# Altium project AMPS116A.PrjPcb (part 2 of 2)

## Sheet AMPS116A_PowerSupplies.SchDoc: Power Supplies
size Letter; Date: Not shown in title block; ApprovedBy: Not shown in title block; CheckedBy: Not shown in title block; Author: Not shown in title block; CompanyName: Not shown in title block; DrawnBy: GJS; Engineer: Not shown in title block; Organization: Not shown in title block; Address1: Not shown in title block; Address2: Not shown in title block; Address3: Not shown in title block; Address4: Not shown in title block; DocumentNumber: 5; SheetNumber: 5; SheetTotal: 6; PageSetup: Record=PageOptions¦CenterHorizontal=True¦CenterVertical=True¦PrintScale=0.70¦XCorrection=1.00¦YCorrection=1.00¦PrintKind=0¦BorderSize=5000000¦LeftOffset=0¦BottomOffset=0¦Orientation=2¦PaperLength=1000¦PaperWidth=1000¦Scale=100¦PaperSource=15¦PrintQuality=600¦MediaType=1¦DitherType=10¦PrintScaleMode=1¦PaperKind=Letter
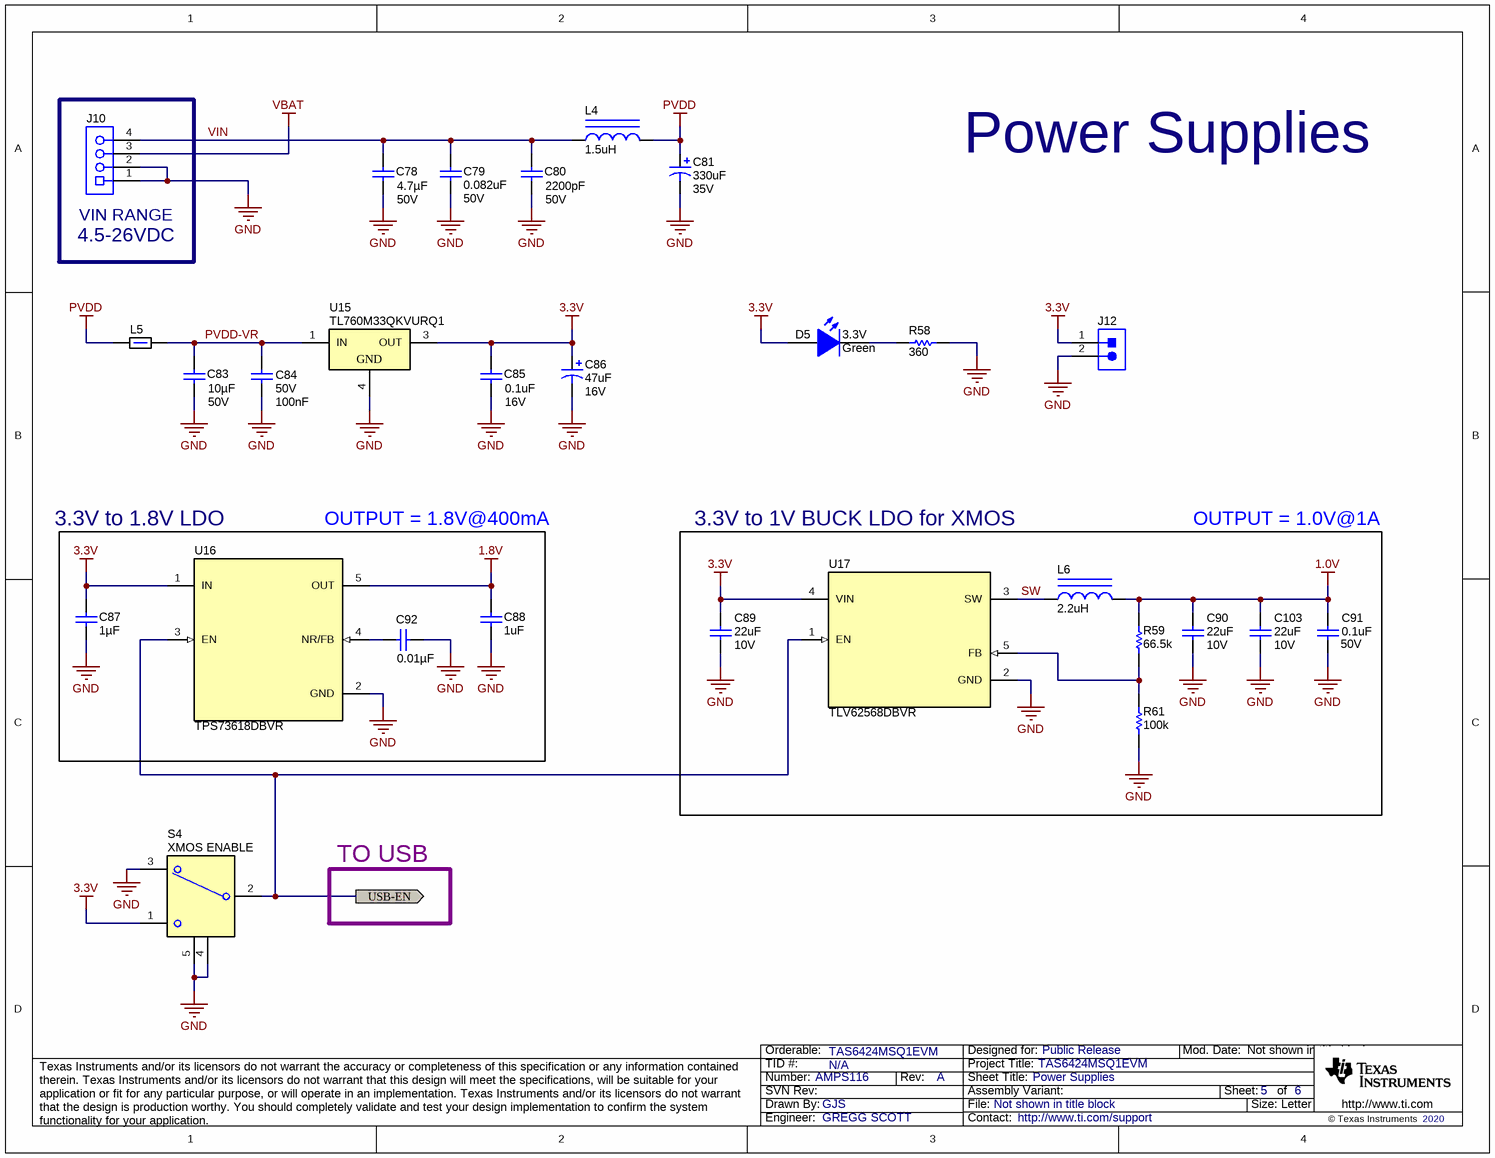
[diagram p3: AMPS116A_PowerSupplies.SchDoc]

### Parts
C78  VDC_V: 50V  ValueDisplayed: 4.7µF  [1210_280]  (hidden comment: C1210C475K5RACAUTO)
C79  ValueDisplayed: 0.082uF  VDC_V: 50V  [0805L]  (hidden comment: Capacitor)
C80  VDC_V: 50V  ValueDisplayed: 2200pF  [0805L]  (hidden comment: 08055A222JAT2A)
C81  ValueDisplayed: 330uF  VDC_V: 35V  [BT_1000x2000]  (hidden comment: +)
C83  VDC_V: 50V  ValueDisplayed: 10µF  [1206_190L]  (hidden comment: UMK316BBJ106KL-T)
C84  Cap_F: 100nF  VDC_V: 50V  [0603L]  (hidden comment: C0603C104J5RACTU)
C85  VDC_V: 16V  ValueDisplayed: 0.1uF  [0402L]  (hidden comment: C0402C104K4RACAUTO)
C86  ValueDisplayed: 47uF  VDC_V: 16V  [FC_500x1100]  (hidden comment: Cap_Polarized)
C87  ValueDisplayed: 1µF  [0603L]  (hidden comment: CL10B105MO8NNWC)
C88  ValueDisplayed: 1uF  [0402L]  (hidden comment: GRM152R60J105ME15D)
C89  VDC_V: 10V  ValueDisplayed: 22uF  [0603L]  (hidden comment: C1608X5R1A226M080AC)
C90  VDC_V: 10V  ValueDisplayed: 22uF  [0603L]  (hidden comment: C1608X5R1A226M080AC)
C91  VDC_V: 50V  ValueDisplayed: 0.1uF  [0402L]  (hidden comment: C1005X7R1H104K050BB)
C92  ValueDisplayed: 0.01µF  [0402L]  (hidden comment: 0402B103K6R3CT)
C103  VDC_V: 10V  ValueDisplayed: 22uF  [0603L]  (hidden comment: C1608X5R1A226M080AC)
D5  3.3V  value Green  [LTST-C170KGKT_Green]
J10  Receptacle_4x1  [TERM_BLK_ED555-4DS]  (value not drawn)
J12  DNP  [Sullins_PBC02SAAN]  (value not drawn)
L4  ValueDisplayed: 1.5uH  [VCMT053T]  (hidden comment: VCMT053T-1R5MN5)
L5  Ferrite_Bead  [NFZ2M]  (value not drawn)
L6  ValueDisplayed: 2.2uH  [1008]  (hidden comment: LQM2HPN2R2MG0L)
R58  ValueDisplayed: 360  [0402L]  (hidden comment: Resistor)
R59  ValueDisplayed: 66.5k  [0603L]  (hidden comment: RC0603FR-0766K5L)
R61  ValueDisplayed: 100k  [0603L]  (hidden comment: RC0603FR-07100KL)
S4  XMOS ENABLE  [SW_FT1D-4M-Z]
U15  PartNumber: TL760M33QKVURQ1  [KVU0003A_N]  (hidden comment: TI-TL7X0MXX-Q1KVU3)
U16  PartNumber: TPS73618DBVR  [DBV0005A_N]  (hidden comment: TPS736xxDBV)
U17  TLV62568DBVR  [DBV0005A_N]

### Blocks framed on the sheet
4.5-26VDC: J10
3.3V to 1.8V LDO: C87 C88 C92 U16
3.3V to 1V BUCK LDO for XMOS: C89-C91 C103 L6 R59 R61 U17

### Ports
USB-EN (out)

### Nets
1.0V: C90.1 C91.1 C103.1 L6.2 R59.2
1.8V: C88.2 U16.5(OUT)
3.3V: C85.2 C86.1(+) C87.2 C89.1 D5.1(A) J12.1 S4.1 U15.3(OUT) U16.1(IN) U17.4(VIN)
GND: C78.1 C79.1 C80.2 C81.2(-) C83.2 C84.1 C85.1 C86.2(-) C87.1 C88.1 C89.2 C90.2 C91.2 C92.1 C103.2 J10.1 J10.2 J12.2 R58.2 R61.1 S4.3 S4.4 S4.5 U15.4(GND) U16.2(GND) U17.2(GND)
PVDD: C81.1(+) L4.2 L5.1
VBAT: J10.3
PVDD-VR: C83.1 C84.2 L5.2 U15.1(IN)
SW: L6.1 U17.3(SW)
USB-EN: S4.2(COM) U16.3(EN) U17.1(EN) ; port USB-EN
VIN: C78.2 C79.2 C80.1 J10.4 L4.1
NetC92_2: C92.2 U16.4(NR/FB)
NetD5_2: D5.2(K) R58.1
NetR59_1: R59.1 R61.2 U17.5(FB)

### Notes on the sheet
- Power Supplies
- (near J10) VIN RANGE
- OUTPUT = 1.8V@400mA
- OUTPUT = 1.0V@1A
- TO USB

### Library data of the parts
C78 = CMP-0079604-1: CAP, CERM, 4.7 µF, 50 V,+/- 10%, X7R, AEC-Q200 Grade 1, 1210; Manufacturer: Kemet; TaMin_C: -55°C; Polarized: N; SizeAreaWB_mm2: 14.7; U/M: EA; Value: 4.7uF; TaMax_C: 125°C; SizeZ_mm: 2.8; SizeX_mm: 3.2; SizeY_mm: 2.5; Cap_Case: 1210; SizeArea_mm2: 8; AEC Qualified: Y; AEC Grade: 1; AEC Category: Q200
C79 = CMP-0007669-2: CAP, CERM, 0.082 uF, 50 V, +/- 10%, X7R, 0805; PartNumber: 08055C823KAT2A; Manufacturer: AVX; Polarized: N; U/M: EA; Cap_F: 82nF; ESR_ohm: 0.026; Value1: 0.026 ohm; TaMin_C: -55°C; TaMax_C: 125°C; Cap_Case: 0805; AEC Category: Q200; SizeArea_mm2: 2.5; SizeAreaWB_mm2: 6.75; SizeX_mm: 2; SizeY_mm: 1.25; SizeZ_mm: 1.45
C80 = CMP-0007601-2: CAP, CERM, 2200 pF, 50 V, +/- 5%, C0G/NP0, 0805; Manufacturer: AVX; TaMin_C: -55°C; ESR_ohm: 0.08; Polarized: N; SizeAreaWB_mm2: 6.75; Value1: 0.08 ohm; U/M: EA; Value: 2200pF; TaMax_C: 125°C; SizeZ_mm: 1.45; SizeX_mm: 2; SizeY_mm: 1.25; Cap_Case: 0805; SizeArea_mm2: 2.5; Cap_F: 2.2nF; AEC Category: Q200
C81 = CMP-0010530-2: CAP, AL, 330 uF, 35 V, +/- 20%, AEC-Q200 Grade 1, TH; PartNumber: UBT1V331MPD1TD; Manufacturer: Nichicon; Polarized: Y; CompType: Capacitor; Value: 330uF; U/M: EA; Cap_F: 330µF; Value1: Unknown; TaMin_C: -40°C; TaMax_C: 125°C; Cap_Case: 10x20mm; AEC Category: Q200; AEC Grade: 1; SizeArea_mm2: 100; SizeAreaWB_mm2: 144; SizeX_mm: 10; SizeZ_mm: 22
C83 = CMP-0086153-1: CAP, CERM, 10 µF, 50 V,+/- 10%, X5R, 1206; Manufacturer: Taiyo Yuden; Polarized: N; SizeX_mm: 3.2; TaMax_C: 85°C; SizeY_mm: 1.6; AEC Category: Q200; SizeArea_mm2: 5.12; Cap_Case: 1206; SizeAreaWB_mm2: 10.92; TaMin_C: -55°C; SizeZ_mm: 1.9; U/M: EA; Value: 10uF
C84 = CMP-0006858-4: CAP, CERM, 0.1 uF, 50 V, +/- 5%, X7R, 0603; Manufacturer: Kemet; TaMin_C: -55°C; Polarized: N; SizeAreaWB_mm2: 4.68; Value1: Unknown; U/M: EA; Value: 0.1uF; TaMax_C: 125°C; SizeZ_mm: 1; SizeX_mm: 1.6; SizeY_mm: 0.8; Cap_Case: 0603; SizeArea_mm2: 1.28; AEC Category: Q200
C85 = CMP-0006237-2: CAP, CERM, 0.1 uF, 16 V, +/- 10%, X7R, AEC-Q200 Grade 1, 0402; Manufacturer: Kemet; TaMin_C: -55°C; Polarized: N; SizeAreaWB_mm2: 3; Value1: Unknown; U/M: EA; Value: 0.1uF; TaMax_C: 125°C; SizeZ_mm: 0.6; SizeX_mm: 1; SizeY_mm: 0.5; Cap_Case: 0402; AEC Qualified: Y; Cap_F: 100nF; AEC Category: Q200
C86 = CMP-0010336-1: CAP, AL, 47 uF, 16 V, +/- 20%, 0.8 ohm, AEC-Q200 Grade 2, TH; PartNumber: EEU-FC1C470; Manufacturer: Panasonic; Polarized: Y; CompType: Capacitor; Value: 47uF; U/M: EA; Cap_F: 47µF; ESR_ohm: 8d; Value1: 0.8 ohm; IRMS_A: 1.75dA; TaMin_C: -55°C; TaMax_C: 105°C; Cap_Case: 5x11mm; AEC Category: Q200; AEC Grade: 2; SizeArea_mm2: 25; SizeAreaWB_mm2: 49; SizeX_mm: 5; SizeZ_mm: 12
C87 = CMP-0082012-1: CAP, CERM, 1 µF, 16 V,+/- 20%, X7R, 0603; Manufacturer: Samsung; SizeAreaWB_mm2: 4.68; SizeArea_mm2: 1.28; AEC Qualified: N; AEC Category: Q200; Value: 1uF; TaMax_C: 125°C; SizeZ_mm: 1; TaMin_C: -55°C; VDC_V: 16V; SizeY_mm: 0.8; U/M: EA; CompType: Capacitor; SizeX_mm: 1.6; Cap_Case: 0603
C88 = CMP-0006372-2: CAP, CERM, 1 uF, 6.3 V, +/- 20%, X5R, 0402; Manufacturer: MuRata; TaMin_C: -55°C; Polarized: N; SizeAreaWB_mm2: 3; Value1: Unknown; U/M: EA; Value: 1uF; TaMax_C: 85°C; SizeZ_mm: 0.6; SizeX_mm: 1; SizeY_mm: 0.5; Cap_Case: 0402; Value2: 6.3V; CompType: Capacitor; Cap_F: 1µF; AEC Category: Q200
C89 C90 C103 = CMP-0007005-5: CAP, CERM, 22 uF, 10 V, +/- 20%, X5R, 0603; Manufacturer: TDK; TaMin_C: -55°C; ESR_ohm: 3.71m; Polarized: N; SizeAreaWB_mm2: 4.68; Value1: 0.00371 ohm; U/M: EA; Value: 22uF; TaMax_C: 85°C; SizeZ_mm: 1; SizeX_mm: 1.6; SizeY_mm: 0.8; Cap_Case: 0603; SizeArea_mm2: 1.28; CompType: Capacitor; Cap_F: 22µF; IRMS_A: 2.69936A; AEC Category: Q200
C91 = CMP-0006297-2: CAP, CERM, 0.1 uF, 50 V, +/- 10%, X7R, 0402; Manufacturer: TDK; TaMin_C: -55°C; Polarized: N; SizeAreaWB_mm2: 3; Value1: 0.039064 ohm; U/M: EA; Value: 0.1uF; TaMax_C: 125°C; SizeZ_mm: 0.6; SizeX_mm: 1; SizeY_mm: 0.5; Cap_Case: 0402; Cap_F: 100nF; AEC Category: Q200; ESR_ohm: 0.039064; IRMS_A: 8.14669dA
C92 = CMP-0860544-1: CAP, CERM, 0.01 µF, 6.3 V,+/- 10%, X7R, 0402; Manufacturer: Walsin; Value: 0.01uF; SizeY_mm: 0.5; SizeX_mm: 1; SizeZ_mm: 0.6; AEC Category: Q200; Value2: 6.3V; SizeAreaWB_mm2: 3; TaMax_C: 125°C; U/M: EA; Cap_Case: 0402; AEC Qualified: N; Cap_F: 10nF; TaMin_C: -55°C
D5 = CMP-0002888-2: LED, Green, SMD; Manufacturer: Lite-On; PartNumber: LTST-C170KGKT; Value1: W; Vf_V: 2V; Type: AlInGaP; Io_A: 20mA
J10 = CMP-0074917-1: Terminal Block, 3.5mm Pitch, 4x1, TH; PartNumber: ED555/4DS; Manufacturer: On-Shore Technology; Pitch_mm: 3.5; Gender: Female; Shrouded: N; Row_Count: 1; ContactFinish: Brass; Current_A: 6A; Voltage_V: 150V; Cert_CULUS: Y; CNHeader: False; CT: True; Green_Lifecycle: Not Set; Green_REACh: Incomplete
J12 = CMP-0054566-1: Header, 100mil, 2x1, Gold, TH; PartNumber: PBC02SAAN; Manufacturer: Sullins Connector Solutions; Cert_UL: Y; CNHeader: TRUE; CT: FALSE; Current_A: 3A; Gender: Male; Green_Lifecycle: Active; Green_REACh: Passed; Pitch_mm: 2.54; Row_Count: 1; Shrouded: N; Voltage_V: 1.8kV
L4 = CMP-0059922-1: Inductor, 1.5 uH, 5.5 A, 0.017 ohm, AEC-Q200 Grade 0, SMD; Manufacturer: Cyntec; Isat: 5.5A @ 30% inductance drop; Irms: 7.4A @ 40C rise; SizeAreaWB_mm2: 54.0125; DCR_ohm: 0.017; Value: 1.5uH; Imax_A: 5.5A; SizeZ_mm: 3; SizeX_mm: 5.45; SizeY_mm: 5.25; SizeArea_mm2: 28.6125; Ind_H: 1.5µH; AEC Qualified: Y; AEC Grade: 0; AEC Category: Q200
L5 = CMP-0003430-1: Ferrite Bead, 180 ohm @ 100 MHz, 3.4 A, 0806; PartNumber: NFZ2MSM181SN10L; Manufacturer: MuRata; Value: 180 ohm; Imax_A: 3.4A; DCR_ohm: 0.025; Value1: 0.025 ohm; ZTyp@100MHz_Ohm: 180
L6 = CMP-0058752-1: Inductor, Multilayer, Ferrite, 2.2 uH, 1.3 A, 0.08 ohm, SMD; Manufacturer: MuRata; Irms: 1.3A @ 40C rise; Green_Lifecycle: Active; SizeAreaWB_mm2: 10.5; DCR_ohm: 0.08; Green_REACh: Passed; Value: 2.2uH; Imax_A: 1.3A; SizeZ_mm: 1.2; SizeX_mm: 2.5; SizeY_mm: 2; SizeArea_mm2: 5; Ind_H: 2.2µH; AEC Category: Q200
R58 = CMP-0026910-3: RES, 360, 5%, 0.063 W, AEC-Q200 Grade 0, 0402; PartNumber: CRCW0402360RJNED; Manufacturer: Vishay-Dale; Value: 360; Value_Code: 360R; Power_W: 63mW; Value2: 0.063W; VDC_V: 50V; TempCo: 200 ppm/C; EIA_Code: E24; AEC Category: Q200; AEC Grade: 0; AEC Qualified: Y; SizeArea_mm2: 0.5; SizeX_mm: 1; SizeZ_mm: 0.6
R59 = CMP-0023232-5: RES, 66.5 k, 1%, 0.1 W, 0603; Manufacturer: Yageo; Power_W: 100mW; TempCo: 100 ppm/C; Value_Code: 66k5; Value: 66.5k; EIA_Code: E96; SizeZ_mm: 1; Value2: 0.1W; SizeArea_mm2: 1.28; AEC Qualified: N; VDC_V: 75V; AEC Category: Q200; SizeAreaWB_mm2: 4.68; SizeX_mm: 1.6; SizeY_mm: 0.8
R61 = CMP-0022735-5: RES, 100 k, 1%, 0.1 W, 0603; Manufacturer: Yageo; Power_W: 100mW; TempCo: 100 ppm/C; Value: 100k; EIA_Code: E96; SizeX_mm: 1.6; SizeY_mm: 0.8; SizeZ_mm: 1; Value2: 0.1W; SizeArea_mm2: 1.28; AEC Qualified: N; VDC_V: 75V; AEC Category: Q200; SizeAreaWB_mm2: 4.68
S4 = CMP-0002268-2: Switch, SPDT, On-On, 1 Pos, 0.4A, 28 VDC, TH; PartNumber: FT1D-4M-Z; Manufacturer: Copal Electronics; PositionCount: 2; CurrentRating_mA: 400A; VDC_V: 28V
U15 = CMP-0036772-2: Single Output Automotive LDO, 500 mA, Fixed 3.3 V Output, 3.8 to 26 V Input, 3-pin PFM (KVU), -40 to 125 degC, Green (RoHS & no Sb/Br); Manufacturer: Texas Instruments; Accuracy(%): 3; Fixed Output Options(V): 3.3; Iout(Max)(A): 0.5; Iq(Typ)(mA): 20; SubFamily: Single Channel LDO; Vdo(Typ)(mV): 500; Vin(Max)(V): 26; Vin(Min)(V): 3.8
U16 = CMP-0036854-2: Single Output LDO, 400mA, Adj.(1.2 to 5.5V), Cap free, Low Noise, Reverse Current Protection, DBV0005A (SOT-23-5); Manufacturer: Texas Instruments; Accuracy(%): 1; Eco-Plan: Green (RoHS & no Sb/Br); Fixed Output Options(V): 1.8; Iout(Max)(A): 0.4; Iq(Typ)(mA): 0.3; Rating: Catalog; SubFamily: Single Channel LDO; Vdo(Typ)(mV): 75; Vin(Max)(V): 5.5; Vin(Min)(V): 1.7; AEC Category: Q200; AEC Qualified: N; CompType: IC; Green_Lifecycle: Active; Green_REACh: Passed; SizeArea_mm2: 8.12; SizeAreaWB_mm2: 14.82; SizeX_mm: 2.8; SizeY_mm: 2.9; SizeZ_mm: 1.45
U17 = CMP-0013046-2: 1-A High Efficiency Step-Down Converter in SOT23-5 Package, DBV005A, DBV0005A (SOT-5); Manufacturer: Texas Instruments; Alternate PartNumber: TLV62568DBVT; SizeX_mm: 2.8; SizeY_mm: 2.9; CompType: IC; SizeZ_mm: 1.45; SizeArea_mm2: 8.12; SizeAreaWB_mm2: 14.82; U/M: EA

## Sheet AMPS116A_EVM_Hardware.SchDoc: Hardware
size Letter; Date: Not shown in title block; ApprovedBy: Not shown in title block; CheckedBy: Not shown in title block; Author: Not shown in title block; CompanyName: Not shown in title block; DrawnBy: GJS; Engineer: Not shown in title block; Organization: Not shown in title block; Address1: Not shown in title block; Address2: Not shown in title block; Address3: Not shown in title block; Address4: Not shown in title block; DocumentNumber: 6; Revision: Use project parameter SCH_Rev; SheetNumber: 6; SheetTotal: 6; PageSetup: Record=PageOptions¦CenterHorizontal=True¦CenterVertical=True¦PrintScale=1.00¦XCorrection=1.00¦YCorrection=1.00¦PrintKind=0¦BorderSize=5000000¦LeftOffset=0¦BottomOffset=0¦Orientation=2¦PaperLength=1000¦PaperWidth=1000¦Scale=100¦PaperSource=15¦PrintQuality=600¦MediaType=1¦DitherType=10¦PaperKind=Letter¦PrintScaleMode=1
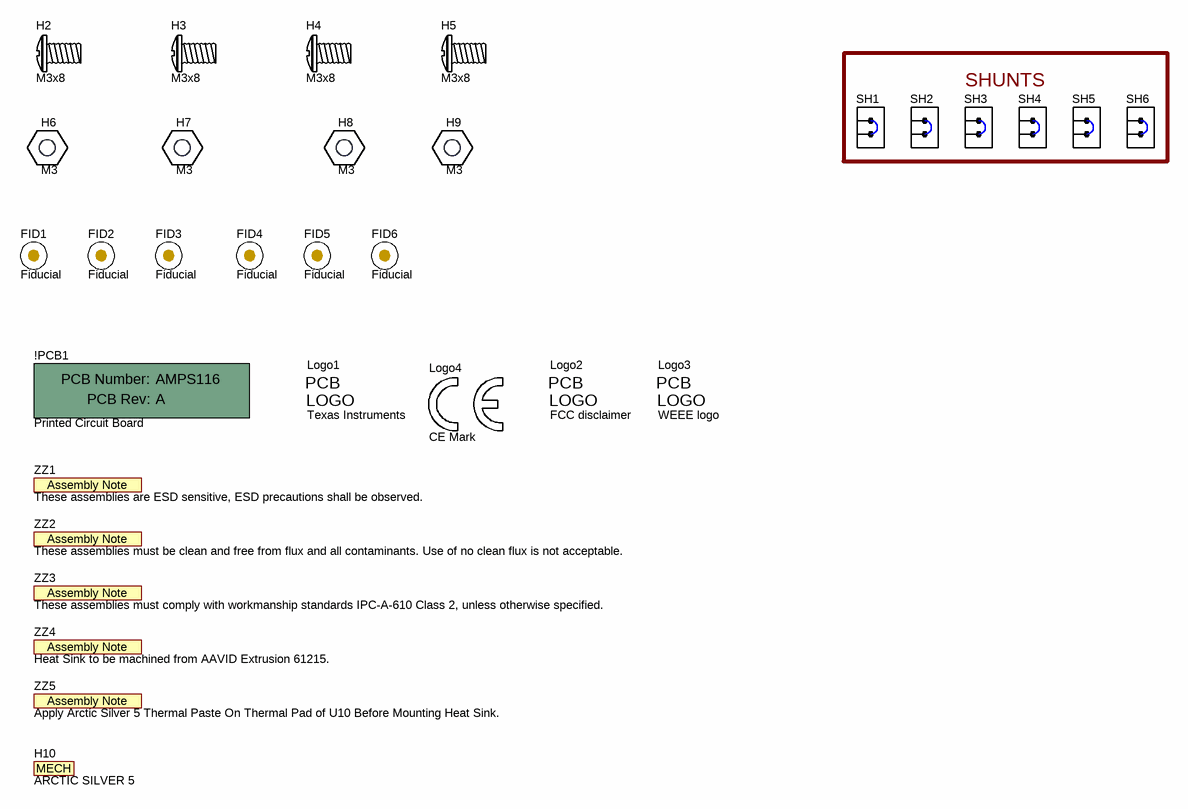
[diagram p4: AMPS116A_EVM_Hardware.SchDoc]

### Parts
!PCB1  Printed Circuit Board  (mechanical)
FID1  CompType: Fiducial  [Fiducial6.4-20]  (hidden comment: DNP)
FID2  CompType: Fiducial  [Fiducial6.4-20]  (hidden comment: DNP)
FID3  CompType: Fiducial  [Fiducial6.4-20]  (hidden comment: DNP)
FID4  CompType: Fiducial  [Fiducial6.4-20]  (hidden comment: DNP)
FID5  CompType: Fiducial  [Fiducial6.4-20]  (hidden comment: DNP)
FID6  CompType: Fiducial  [Fiducial6.4-20]  (hidden comment: DNP)
H2  M3x8  [APM_RM3X8MM 2701]  (mechanical)
H3  M3x8  [APM_RM3X8MM 2701]  (mechanical)
H4  M3x8  [APM_RM3X8MM 2701]  (mechanical)
H5  M3x8  [APM_RM3X8MM 2701]  (mechanical)
H6  M3  [Keystone_24434]
H7  M3  [Keystone_24434]
H8  M3  [Keystone_24434]
H9  M3  [Keystone_24434]
H10  ARCTIC SILVER 5  (mechanical)
Logo1  Texas Instruments  [TI_Stacked_Overlay_Small]  (no BOM)
Logo2  FCC disclaimer  [FCC_disclaimer_stacked]  (no BOM)
Logo3  WEEE logo  [WEEE_Minimum]  (no BOM)
Logo4  CE Mark  [CE_Mark_5mm]  (no BOM)
SH1  SNT-100-BK-G  [SNT-100-BK-G]  (value not drawn)
SH2  SNT-100-BK-G  [SNT-100-BK-G]  (value not drawn)
SH3  SNT-100-BK-G  [SNT-100-BK-G]  (value not drawn)
SH4  SNT-100-BK-G  [SNT-100-BK-G]  (value not drawn)
SH5  SNT-100-BK-G  [SNT-100-BK-G]  (value not drawn)
SH6  SNT-100-BK-G  [SNT-100-BK-G]  (value not drawn)
ZZ1  These assemblies are ESD sensitive, ESD precautions shall be observed.  [AssemblyNote]  (no BOM)
ZZ2  These assemblies must be clean and free from flux and all contaminants. Use of no clean flux is not acceptable.  [AssemblyNote]  (no BOM)
ZZ3  These assemblies must comply with workmanship standards IPC-A-610 Class 2, unless otherwise specified.  [AssemblyNote]  (no BOM)
ZZ4  Heat Sink to be machined from AAVID Extrusion 61215.  [AssemblyNote]  (no BOM)
ZZ5  Apply Arctic Silver 5 Thermal Paste On Thermal Pad of U10 Before Mounting Heat Sink.  [AssemblyNote]  (no BOM)

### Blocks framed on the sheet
SHUNTS: SH1-SH6

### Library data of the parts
!PCB1 = CMP-0003618-2: PartNumber: AMPS116; Manufacturer: Any
FID1-FID6 = CMP-0077181-1: Fiducial mark.  There is nothing to buy or mount.
H2-H5 = CMP-0003717-1: MACHINE SCREW PAN PHILLIPS M3; Manufacturer: APM HEXSEAL; Key: RM3X8MM 2701; CompType: Standoff
H6-H9 = CMP-0003665-1: Standoff, Hex, 12mm, M3, Aluminum; Manufacturer: Keystone; Key: 24434
H10 = CMP-0080604-2: Arctic Silver 5 Thermal Paste; Manufacturer: ARTIC SILVER, INC.; CompType: Mechanical
Logo1 = CMP-0074838-1: Texas Instrument Corporate Signature; Library Reference: Logo; SymbolCreator: a0412235; Lib Reference: TI_Logo
Logo2 = CMP-0074847-1: FCC_disclaimer; Library Reference: Logo
Logo3 = CMP-0074769-1
Logo4 = CMP-0074844-1: SymbolCreator: a0412235
SH1-SH6 = CMP-0003623-3: Shunt, 100mil, Gold plated, Black; Alternate PartNumber: 969102-0000-DA; Manufacturer: Samtec; Alternate Manufacturer: 3M; Value: 1x2
ZZ1 = CMP-0077236-1
ZZ2 = CMP-0077237-1
ZZ3 = CMP-0077238-1
ZZ4 ZZ5 = CMP-0003615-1

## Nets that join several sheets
1.0V: AMPS116A_USB (33 pins), AMPS116A_PowerSupplies (5 pins)
1.8V: AMPS116A_USB (C54.1 C55.1 U4.8 U5.3), AMPS116A_PowerSupplies (C88.2 U16.5)
3.3V: AMPS116A_USB (50 pins), AMPS116A_SPDIF (13 pins), AMPS116A_TAS6424-IO (8 pins), AMPS116A_PowerSupplies (10 pins)
GND: AMPS116A_USB (53 pins), AMPS116A_SPDIF (51 pins), AMPS116A_TAS6424-IO (53 pins), AMPS116A_PowerSupplies (26 pins)
PVDD: AMPS116A_TAS6424-IO (16 pins), AMPS116A_PowerSupplies (C81.1 L4.2 L5.1)
VBAT: AMPS116A_TAS6424-IO (C11.2 J13.1 U1.3), AMPS116A_PowerSupplies (J10.3)
FSYNC: AMPS116A_SPDIF (J7.2), AMPS116A_TAS6424-IO (U1.14)
MCLK: AMPS116A_SPDIF (J5.2), AMPS116A_TAS6424-IO (U1.12)
SCL: AMPS116A_USB (R11.2 U2.37 U5.12), AMPS116A_TAS6424-IO (J14.1 U1.20)
SCLK: AMPS116A_SPDIF (J6.2), AMPS116A_TAS6424-IO (U1.13)
SDA: AMPS116A_USB (R12.2 U2.38 U5.13), AMPS116A_TAS6424-IO (J14.3 U1.21)
SDIN: AMPS116A_SPDIF (J8.2), AMPS116A_TAS6424-IO (J2.1 U1.15)
USB-EN: AMPS116A_USB (U3.1), AMPS116A_PowerSupplies (S4.2 U16.3 U17.1)
X-BCLK: AMPS116A_USB (R22.2 R29.2), AMPS116A_SPDIF (U10.1)
X-DOUT: AMPS116A_USB (R25.2), AMPS116A_SPDIF (U13.1)
X-LRCK: AMPS116A_USB (R21.2), AMPS116A_SPDIF (U11.1)
X-MCLK: AMPS116A_USB (R14.2 R23.2 R30.2), AMPS116A_SPDIF (U9.1)

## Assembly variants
001: not fitted FID1 FID2 FID3 FID4 FID5 FID6 J12 R2 R4 R52 R56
